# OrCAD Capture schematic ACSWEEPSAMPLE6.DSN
size A
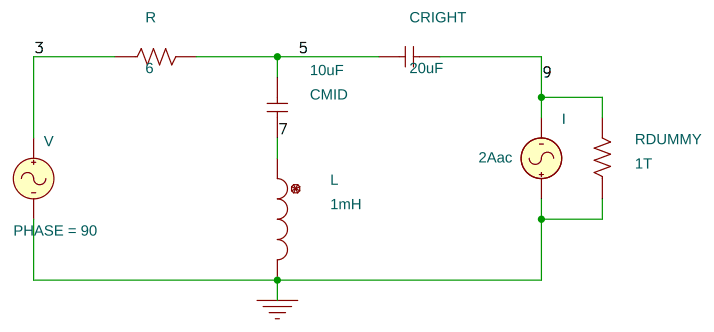
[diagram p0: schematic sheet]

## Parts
CMID  10uF  [RAD/CK05]
CRIGHT  20uF  [RAD/CK05]
I  IAC
L  1mH  [DISC/.350x.175/LS.200x.100/.034]
R  6  [AX/RC05]
RDUMMY  1T  [AX/RC05]
V  VAC

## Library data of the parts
CMID CRIGHT = C
I = IAC: ACMAG: 2Aac; ACPHASE: 330
L = L
R RDUMMY = R
V = VAC: ACPHASE: 90; PHASE: 90

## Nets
0: I.1(+) L.2 RDUMMY.1 V.2(-)
3: R.1 V.1(+)
5: CMID.2 CRIGHT.1 R.2
7: CMID.1 L.1
9: CRIGHT.2 I.2(-) RDUMMY.2
